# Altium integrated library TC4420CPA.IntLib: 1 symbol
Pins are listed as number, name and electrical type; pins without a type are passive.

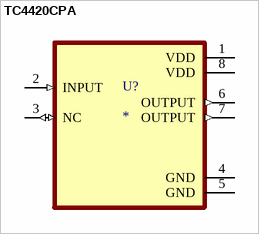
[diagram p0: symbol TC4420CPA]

## TC4420CPA
designator U?
Microchip MOSFET Power Driver 6A 4.5 to 18V Non-Inverting 8-Pin PDIP ¦ Microchip Technology Inc. TC4420CPA
footprint DIP787W46P254L927H533Q8
pins: 1 VDD (power), 2 INPUT (in), 3 NC (io), 4 GND (power), 5 GND (power), 6 OUTPUT (out), 7 OUTPUT (out), 8 VDD (power)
